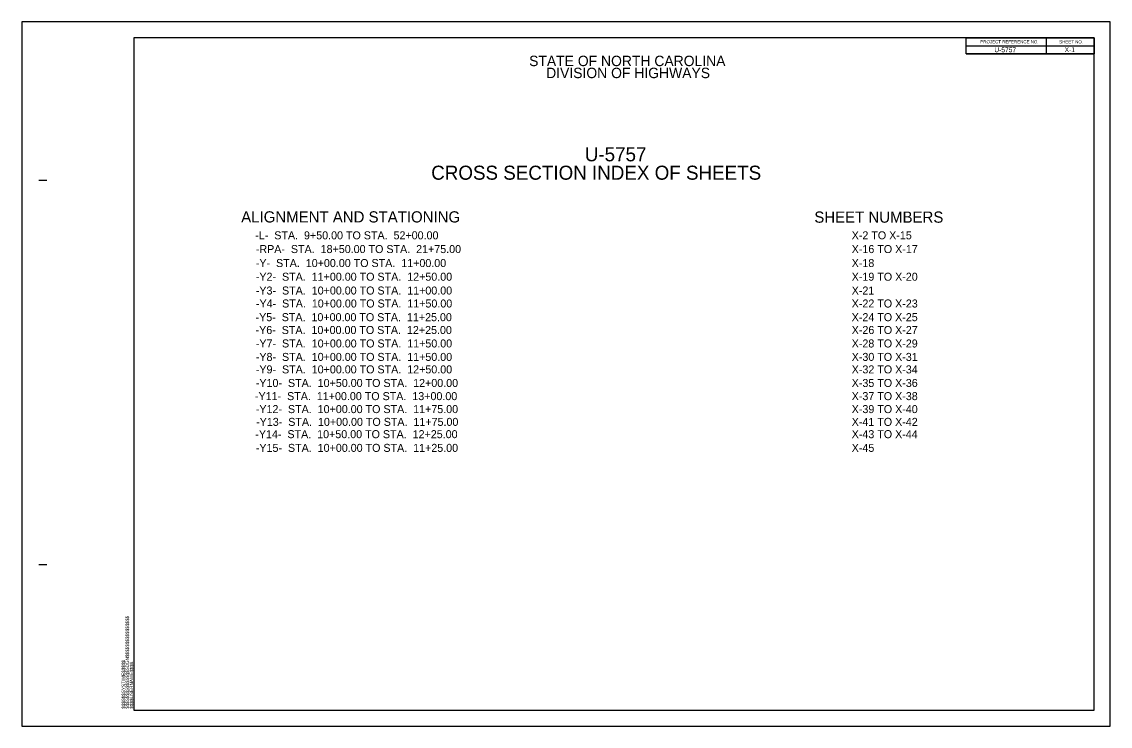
# Model space of a CAD drawing. Extents: x 573852.9 to 573886.9, y -53297.7 to -53275.7.
import ezdxf

# ---------------------------------------------------------------- set-up
doc = ezdxf.new("R2010")
doc.units = 0
for name, color, linetype in [('Sheet Data Field CELL', 7, 'Continuous'), ('Sheet Plot Border Outside CELL', 7, 'Continuous'), ('Sheet Summary CELL', 7, 'Continuous')]:
    doc.layers.add(name, color=color, linetype=linetype)

msp = doc.modelspace()

# ---------------------------------------------------------------- linework, layer by layer
at = {"layer": 'Sheet Plot Border Outside CELL'}
msp.add_lwpolyline([(573852.921, -53297.659), (573886.921, -53297.659), (573886.921, -53275.659), (573852.921, -53275.659)], close=True, dxfattribs=at)
at = {"layer": 'Sheet Summary CELL'}
for p, q in [((573856.421, -53276.159), (573856.421, -53276.968)), ((573884.921, -53276.16), (573884.921, -53276.66)), ((573882.42, -53276.41), (573886.421, -53276.41)), ((573882.42, -53276.66), (573886.421, -53276.66)), ((573853.451, -53280.609), (573853.701, -53280.609)), ((573853.451, -53292.609), (573853.701, -53292.609)), ((573856.421, -53297.159), (573856.421, -53297.159)), ((573856.421, -53297.159), (573856.421, -53297.159)), ((573856.421, -53297.159), (573856.421, -53297.159)), ((573856.421, -53297.159), (573856.421, -53297.159)), ((573856.421, -53297.159), (573856.421, -53297.159)), ((573856.421, -53297.159), (573856.421, -53297.159))]:
    msp.add_line(p, q, dxfattribs=at)
for points in [[(573886.421, -53276.159), (573856.421, -53276.159), (573856.421, -53297.159), (573886.421, -53297.159)], [(573882.42, -53276.159), (573886.421, -53276.159), (573886.421, -53276.66), (573882.42, -53276.66)]]:
    msp.add_lwpolyline(points, close=True, dxfattribs=at)
msp.add_lwpolyline([(573859.171, -53297.159), (573859.171, -53297.159)], dxfattribs=at)

# ---------------------------------------------------------------- texts
at = {"layer": 'Sheet Data Field CELL'}
for s, p in [('U-5757', (573883.301, -53276.61)), ('X-1', (573885.497, -53276.604))]:
    msp.add_text(s, height=0.15, dxfattribs=at).set_placement(p)
at = {"layer": 'Sheet Summary CELL'}
for s, height, p in [('PROJECT REFERENCE NO.', 0.1, (573882.864, -53276.333)), ('SHEET NO.', 0.1, (573885.327, -53276.335)), ('STATE OF NORTH CAROLINA', 0.325, (573868.769, -53277.044)), ('DIVISION OF HIGHWAYS', 0.325, (573869.301, -53277.419)), ('U-5757', 0.439, (573870.508, -53280.017)), ('CROSS SECTION INDEX OF SHEETS', 0.439, (573865.71, -53280.592)), ('ALIGNMENT AND STATIONING', 0.35, (573859.775, -53281.927)), ('SHEET NUMBERS', 0.35, (573877.677, -53281.934)), ('-L-  STA.  9+50.00 TO STA.  52+00.00', 0.25, (573860.214, -53282.453)), ('X-2 TO X-15', 0.25, (573878.845, -53282.453)), ('-RPA-  STA.  18+50.00 TO STA.  21+75.00', 0.25, (573860.232, -53282.882)), ('X-16 TO X-17', 0.25, (573878.845, -53282.882)), ('-Y-  STA.  10+00.00 TO STA.  11+00.00', 0.25, (573860.232, -53283.319)), ('X-18 ', 0.25, (573878.845, -53283.319)), ('-Y2-  STA.  11+00.00 TO STA.  12+50.00', 0.25, (573860.232, -53283.746)), ('X-19 TO X-20', 0.25, (573878.845, -53283.746)), ('-Y3-  STA.  10+00.00 TO STA.  11+00.00', 0.25, (573860.232, -53284.177)), ('X-21', 0.25, (573878.845, -53284.177)), ('-Y4-  STA.  10+00.00 TO STA.  11+50.00', 0.25, (573860.235, -53284.582)), ('X-22 TO X-23', 0.25, (573878.845, -53284.582)), ('-Y5-  STA.  10+00.00 TO STA.  11+25.00', 0.25, (573860.224, -53285.009)), ('X-24 TO X-25', 0.25, (573878.845, -53285.009)), ('-Y6-  STA.  10+00.00 TO STA.  12+25.00', 0.25, (573860.224, -53285.41)), ('X-26 TO X-27', 0.25, (573878.845, -53285.41)), ('-Y7-  STA.  10+00.00 TO STA.  11+50.00', 0.25, (573860.232, -53285.83)), ('X-28 TO X-29', 0.25, (573878.845, -53285.83)), ('-Y8-  STA.  10+00.00 TO STA.  11+50.00', 0.25, (573860.232, -53286.25)), ('X-30 TO X-31', 0.25, (573878.845, -53286.25)), ('-Y9-  STA.  10+00.00 TO STA.  12+50.00', 0.25, (573860.232, -53286.64)), ('X-32 TO X-34', 0.25, (573878.845, -53286.64)), ('-Y10-  STA.  10+50.00 TO STA.  12+00.00', 0.25, (573860.232, -53287.064)), ('X-35 TO X-36', 0.25, (573878.845, -53287.064)), ('-Y11-  STA.  11+00.00 TO STA.  13+00.00', 0.25, (573860.206, -53287.475)), ('X-37 TO X-38', 0.25, (573878.845, -53287.475)), ('-Y12-  STA.  10+00.00 TO STA.  11+75.00', 0.25, (573860.232, -53287.88)), ('X-39 TO X-40', 0.25, (573878.845, -53287.88)), ('-Y13-  STA.  10+00.00 TO STA.  11+75.00', 0.25, (573860.241, -53288.279)), ('X-41 TO X-42', 0.25, (573878.845, -53288.279)), ('-Y14-  STA.  10+50.00 TO STA.  12+25.00', 0.25, (573860.216, -53288.663)), ('X-43 TO X-44', 0.25, (573878.845, -53288.663)), ('-Y15-  STA.  10+00.00 TO STA.  11+25.00', 0.25, (573860.232, -53289.091)), ('X-45', 0.25, (573878.845, -53289.091))]:
    msp.add_text(s, height=height, dxfattribs=at).set_placement(p)
for s, p in [('$$$$$$$$$$$$$$$$DGN$$$$$$$$$$$$$$$$', (573856.268, -53297.112)), ('$$$$$$SYSTIME$$$$$', (573856.147, -53297.112)), ('$$$$USERNAME$$$$', (573856.399, -53297.111))]:
    msp.add_text(s, height=0.105, rotation=90, dxfattribs=at).set_placement(p)

doc.saveas('drawing.dxf')
